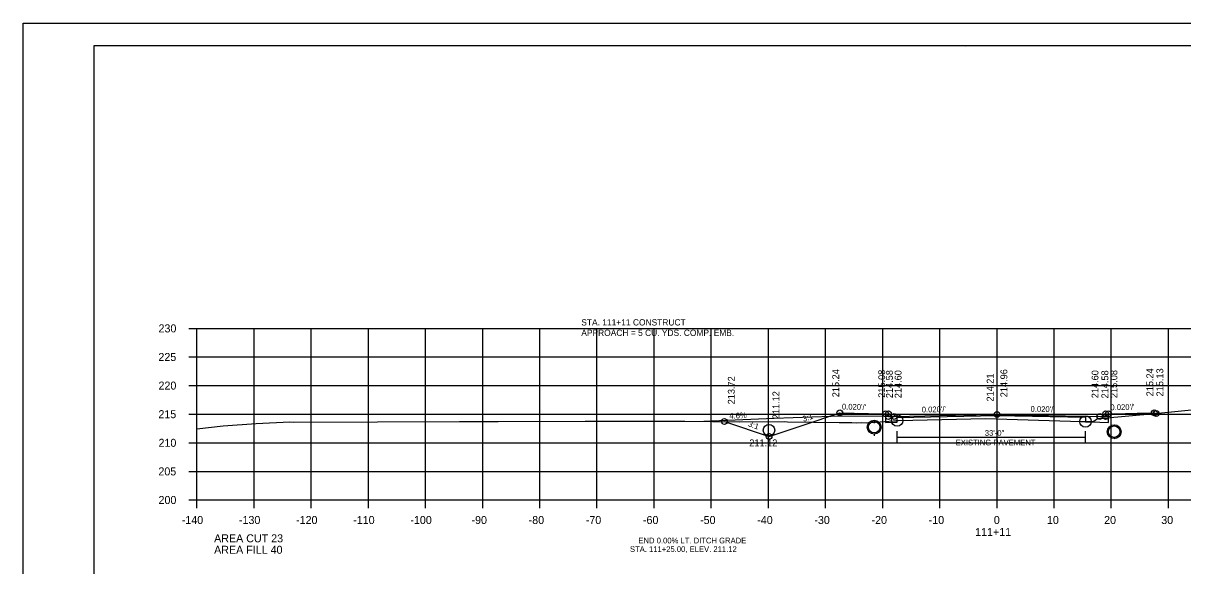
# Model space of a CAD drawing. Extents: x 1368968 to 1369915, y 377395 to 380381.
# Drawn here: x 1369581.4 to 1369784.3, y 377513.2 to 377608 of the extents above; entities that cross this region are included whole.
import ezdxf

# ---------------------------------------------------------------- set-up
doc = ezdxf.new("R2010")
doc.units = 0
for name, color, linetype in [('S_BORDER_NO_PLOT', 7, 'Continuous'), ('S_BREAKLINE_ANNOT', 7, 'Continuous'), ('S_BRIDGE', 7, 'Continuous'), ('S_BRIDGE_ANNOT', 7, 'Continuous'), ('S_CONTOUR_MAJOR', 7, 'Continuous'), ('S_CONTOUR_MINOR', 7, 'Continuous'), ('S_CROSS_DRAIN', 7, 'Continuous'), ('S_CTL_TABLE', 7, 'Continuous'), ('S_CURB_ANNOT', 7, 'Continuous'), ('S_DITCHLINE_ANNOT', 7, 'Continuous'), ('S_DROP_INLET', 7, 'Continuous'), ('S_EXIST_ROW_ANNOT', 7, 'Continuous'), ('S_EXISTING_ALIGNMENT_ANNOT', 7, 'Continuous'), ('S_FENCE', 7, 'Continuous')]:
    doc.layers.add(name, color=color, linetype=linetype)

msp = doc.modelspace()

# ---------------------------------------------------------------- linework, layer by layer
at = {"layer": 'S_BORDER_NO_PLOT'}
msp.add_lwpolyline([(1369732.27, 377539.76), (1369732.28, 377538.25), (1369733.78, 377538.28), (1369734.31, 377538.29), (1369734.31, 377539.12), (1369751.78, 377539.47), (1369767.26, 377539.16), (1369767.26, 377538.33), (1369769.78, 377538.28), (1369771.28, 377538.25), (1369771.29, 377539.76)], dxfattribs=at)
at = {"layer": 'S_BREAKLINE_ANNOT'}
for p, q in [((1369610.38, 377554.68), (1369611.78, 377554.68)), ((1369611.78, 377524.68), (1369611.78, 377554.68)), ((1369610.38, 377549.68), (1369611.78, 377549.68)), ((1369610.38, 377544.68), (1369611.78, 377544.68)), ((1369610.38, 377539.68), (1369611.78, 377539.68)), ((1369610.38, 377534.68), (1369611.78, 377534.68)), ((1369610.38, 377529.68), (1369611.78, 377529.68)), ((1369610.38, 377524.68), (1369611.78, 377524.68)), ((1369611.78, 377524.68), (1369891.78, 377524.68)), ((1369611.78, 377523.28), (1369611.78, 377524.68)), ((1369621.78, 377523.28), (1369621.78, 377524.68)), ((1369631.78, 377523.28), (1369631.78, 377524.68)), ((1369641.78, 377523.28), (1369641.78, 377524.68)), ((1369651.78, 377523.28), (1369651.78, 377524.68)), ((1369661.78, 377523.28), (1369661.78, 377524.68)), ((1369671.78, 377523.28), (1369671.78, 377524.68)), ((1369681.78, 377523.28), (1369681.78, 377524.68)), ((1369691.78, 377523.28), (1369691.78, 377524.68)), ((1369701.78, 377523.28), (1369701.78, 377524.68)), ((1369711.78, 377523.28), (1369711.78, 377524.68)), ((1369721.78, 377523.28), (1369721.78, 377524.68)), ((1369731.78, 377523.28), (1369731.78, 377524.68)), ((1369741.78, 377523.28), (1369741.78, 377524.68)), ((1369751.78, 377523.28), (1369751.78, 377524.68)), ((1369761.78, 377523.28), (1369761.78, 377524.68)), ((1369771.78, 377523.28), (1369771.78, 377524.68)), ((1369781.78, 377523.28), (1369781.78, 377524.68))]:
    msp.add_line(p, q, dxfattribs=at)
at = {"layer": 'S_BRIDGE_ANNOT'}
for p, q in [((1369593.78, 377604.14), (1369909.96, 377604.14)), ((1369593.78, 377398.68), (1369593.78, 377604.14)), ((1369746.3, 377603.88), (1369746.3, 377603.88)), ((1369746.3, 377603.88), (1369746.3, 377603.88))]:
    msp.add_line(p, q, dxfattribs=at)
at = {"layer": 'S_CROSS_DRAIN'}
for p, q in [((1369700.49, 377538.44), (1369712.78, 377539)), ((1369712.78, 377539), (1369722.78, 377539.36)), ((1369732.78, 377539.26), (1369722.78, 377539.36)), ((1369734.31, 377535.69), (1369760.63, 377535.69)), ((1369734.31, 377535.69), (1369767.26, 377535.69))]:
    msp.add_line(p, q, dxfattribs=at)
at = {"layer": 'S_CTL_TABLE'}
msp.add_lwpolyline([(1369611.78, 377537.13), (1369616.39, 377537.67), (1369622.15, 377538.07), (1369628.03, 377538.35), (1369628.65, 377538.3), (1369643.39, 377538.34), (1369657.7, 377538.38), (1369664.36, 377538.43), (1369664.51, 377538.41), (1369679.69, 377538.45), (1369681.36, 377538.46), (1369694.55, 377538.49), (1369697.17, 377538.47), (1369706.8, 377538.37), (1369714.65, 377538.39), (1369715.09, 377538.34), (1369724.17, 377538.23), (1369726.38, 377538.23), (1369727.18, 377538.19), (1369727.99, 377538.2), (1369728.94, 377538.18), (1369733.65, 377538.5), (1369734.15, 377538.55), (1369734.21, 377538.55), (1369734.31, 377538.56), (1369734.49, 377538.57), (1369749.77, 377538.95), (1369766.48, 377538.43), (1369767.26, 377538.41), (1369768.63, 377538.46), (1369768.68, 377538.46), (1369768.71, 377538.48), (1369769.34, 377538.94), (1369770.29, 377539.01), (1369779.39, 377539.78), (1369786.96, 377540.54)], dxfattribs=at)
at = {"layer": 'S_CURB_ANNOT'}
msp.add_lwpolyline([(1369704.08, 377538.4), (1369711.89, 377535.8), (1369717.88, 377537.79), (1369724.27, 377539.92), (1369729.27, 377539.82), (1369732.27, 377539.76), (1369732.51, 377539.76), (1369732.77, 377539.76), (1369732.78, 377539.26), (1369733.78, 377539.28), (1369733.78, 377539.28), (1369744.52, 377539.5), (1369751.78, 377539.64), (1369769.78, 377539.28), (1369770.78, 377539.26), (1369770.79, 377539.76), (1369771.22, 377539.76), (1369771.29, 377539.76), (1369774.29, 377539.82), (1369776.31, 377539.86), (1369779.29, 377539.92), (1369779.46, 377539.86), (1369779.64, 377539.8)], dxfattribs=at)
at = {"layer": 'S_DITCHLINE_ANNOT'}
for p, q in [((1369611.78, 377554.68), (1369891.78, 377554.68)), ((1369611.78, 377524.68), (1369611.78, 377554.68)), ((1369621.78, 377524.68), (1369621.78, 377554.68)), ((1369631.78, 377524.68), (1369631.78, 377554.68)), ((1369641.78, 377524.68), (1369641.78, 377554.68)), ((1369651.78, 377524.68), (1369651.78, 377554.68)), ((1369661.78, 377524.68), (1369661.78, 377554.68)), ((1369671.78, 377524.68), (1369671.78, 377554.68)), ((1369681.78, 377524.68), (1369681.78, 377554.68)), ((1369691.78, 377524.68), (1369691.78, 377554.68)), ((1369701.78, 377524.68), (1369701.78, 377554.68)), ((1369711.78, 377524.68), (1369711.78, 377554.68)), ((1369721.78, 377524.68), (1369721.78, 377554.68)), ((1369731.78, 377524.68), (1369731.78, 377554.68)), ((1369741.78, 377524.68), (1369741.78, 377554.68)), ((1369751.78, 377524.68), (1369751.78, 377554.68)), ((1369761.78, 377524.68), (1369761.78, 377554.68)), ((1369771.78, 377524.68), (1369771.78, 377554.68)), ((1369781.78, 377524.68), (1369781.78, 377554.68)), ((1369611.78, 377549.68), (1369891.78, 377549.68)), ((1369611.78, 377544.68), (1369891.78, 377544.68)), ((1369611.78, 377539.68), (1369891.78, 377539.68)), ((1369611.78, 377534.68), (1369891.78, 377534.68)), ((1369611.78, 377529.68), (1369891.78, 377529.68)), ((1369611.78, 377524.68), (1369891.78, 377524.68))]:
    msp.add_line(p, q, dxfattribs=at)
at = {"layer": 'S_DROP_INLET'}
for p, q in [((1369581.38, 377608.03), (1369914.71, 377608.03)), ((1369730.28, 377538.51), (1369730.28, 377538.34)), ((1369730.28, 377536.09), (1369730.28, 377535.92))]:
    msp.add_line(p, q, dxfattribs=at)
for points in [[(1369581.37, 377608.03), (1369914.71, 377608.03), (1369914.71, 377394.69), (1369581.37, 377394.69)], [(1369827.7, 377604.14), (1369827.7, 377594.26), (1369863.43, 377594.26), (1369863.43, 377591.34), (1369886.63, 377591.34), (1369886.63, 377567), (1369909.96, 377567), (1369909.96, 377398.68), (1369593.78, 377398.68), (1369593.78, 377604.14)]]:
    msp.add_lwpolyline(points, close=True, dxfattribs=at)
for centre, radius in [((1369724.27, 377539.92), 0.5), ((1369732.27, 377539.76), 0.5), ((1369732.77, 377539.76), 0.5), ((1369732.78, 377539.26), 0.5), ((1369733.78, 377539.28), 0.5), ((1369733.78, 377539.28), 0.5), ((1369751.78, 377539.64), 0.5), ((1369769.78, 377539.28), 0.5), ((1369769.78, 377539.28), 0.5), ((1369770.78, 377539.26), 0.5), ((1369770.79, 377539.76), 0.5), ((1369771.29, 377539.76), 0.5), ((1369779.29, 377539.92), 0.5), ((1369779.64, 377539.8), 0.5), ((1369704.08, 377538.4), 0.5), ((1369730.28, 377537.41), 1.21), ((1369734.31, 377538.56), 1), ((1369767.26, 377538.41), 1), ((1369772.29, 377536.62), 1.21), ((1369711.89, 377535.8), 0.5)]:
    msp.add_circle(centre, radius, dxfattribs=at)
at = {"layer": 'S_EXIST_ROW_ANNOT'}
for p, q in [((1369730.28, 377538.3), (1369730.28, 377538.13)), ((1369772.26, 377537.88), (1369772.32, 377537.77)), ((1369772.26, 377537.67), (1369772.32, 377537.56)), ((1369730.28, 377536.3), (1369730.28, 377536.13)), ((1369734.31, 377534.69), (1369734.31, 377536.69)), ((1369734.31, 377534.69), (1369734.31, 377536.69)), ((1369767.26, 377534.69), (1369767.26, 377536.69)), ((1369772.26, 377535.67), (1369772.32, 377535.56)), ((1369772.26, 377535.47), (1369772.32, 377535.35))]:
    msp.add_line(p, q, dxfattribs=at)
for centre in [(1369711.88, 377536.88), (1369730.28, 377537.41), (1369772.29, 377536.62)]:
    msp.add_circle(centre, 1, dxfattribs=at)
at = {"layer": 'S_EXISTING_ALIGNMENT_ANNOT'}
msp.add_line((1369751.78, 377538.89), (1369751.78, 377548.89), dxfattribs=at)

# ---------------------------------------------------------------- texts
at = {"layer": 'S_BRIDGE'}
for s, p in [('230', (1369605.05, 377553.98)), ('225', (1369605.03, 377548.98)), ('220', (1369605.05, 377543.98)), ('215', (1369605.03, 377538.98)), ('210', (1369605.05, 377533.98)), ('205', (1369605.03, 377528.98)), ('200', (1369605.05, 377523.98)), ('-140', (1369609.12, 377520.48)), ('-130', (1369619.12, 377520.48)), ('-120', (1369629.12, 377520.48)), ('-110', (1369639.12, 377520.48)), ('-100', (1369649.12, 377520.48)), ('-90', (1369659.82, 377520.48)), ('-80', (1369669.82, 377520.48)), ('-70', (1369679.82, 377520.48)), ('-60', (1369689.82, 377520.48)), ('-50', (1369699.82, 377520.48)), ('-40', (1369709.82, 377520.48)), ('-30', (1369719.82, 377520.48)), ('-20', (1369729.82, 377520.48)), ('-10', (1369739.82, 377520.48)), ('0', (1369751.22, 377520.48)), ('10', (1369760.52, 377520.48)), ('20', (1369770.52, 377520.48)), ('30', (1369780.52, 377520.48)), ('111+11', (1369747.95, 377518.38)), ('AREA CUT 23', (1369614.78, 377517.28)), ('AREA FILL 40', (1369614.78, 377515.28))]:
    msp.add_text(s, height=1.4, dxfattribs=at).set_placement(p)
at = {"layer": 'S_CONTOUR_MAJOR'}
for s, p in [('END 0.00% LT. DITCH GRADE', (1369689.03, 377517.09)), ('STA. 111+25.00, ELEV. 211.12', (1369687.54, 377515.59))]:
    msp.add_text(s, height=1, dxfattribs=at).set_placement(p)
at = {"layer": 'S_CONTOUR_MINOR'}
for s, p in [('STA. 111+11 CONSTRUCT ', (1369679.03, 377555.19)), ('APPROACH = 5 CU. YDS. COMP. EMB.', (1369679.03, 377553.36))]:
    msp.add_text(s, height=1.1, dxfattribs=at).set_placement(p)
at = {"layer": 'S_CROSS_DRAIN'}
msp.add_text('4.6%', height=1, rotation=2.6332, dxfattribs=at).set_placement((1369704.96, 377538.88))
at = {"layer": 'S_EXIST_ROW_ANNOT'}
for s, height, p in [('33\'-0"', 1, (1369749.64, 377535.9)), ('211.12', 1.2, (1369708.43, 377534.07)), ('EXISTING PAVEMENT', 1, (1369744.54, 377534.23))]:
    msp.add_text(s, height=height, dxfattribs=at).set_placement(p)
at = {"layer": 'S_EXISTING_ALIGNMENT_ANNOT'}
for s, p in [('213.72', (1369705.88, 377541.4)), ('215.24', (1369724.16, 377542.64)), ('215.08', (1369732.2, 377542.55)), ('214.58', (1369733.55, 377542.48)), ('214.60', (1369735.07, 377542.47)), ('214.21', (1369751.18, 377541.89)), ('214.96', (1369753.58, 377542.64)), ('214.60', (1369769.53, 377542.47)), ('214.58', (1369771.26, 377542.44)), ('215.08', (1369772.83, 377542.49)), ('215.24', (1369779.12, 377542.8)), ('215.13', (1369780.87, 377542.79)), ('211.12', (1369713.69, 377538.8))]:
    msp.add_text(s, height=1.2, rotation=90, dxfattribs=at).set_placement(p)
at = {"layer": 'S_FENCE'}
for s, rotation, p in [('3:1', 18.4339, (1369717.92, 377538.33)), ("0.020'/'", 358.8543, (1369724.63, 377540.51)), ("0.020'/'", 1.1458, (1369738.62, 377539.98)), ("0.020'/'", 358.8542, (1369757.64, 377540.12)), ("0.020'/'", 1.1457, (1369771.63, 377540.37)), ('3:1', 341.5639, (1369708.15, 377537.57))]:
    msp.add_text(s, height=1, rotation=rotation, dxfattribs=at).set_placement(p)

doc.saveas('drawing.dxf')
